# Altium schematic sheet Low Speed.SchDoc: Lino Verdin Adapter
size A3; Organization: Toradex AG; Address1: Ebenaustrasse 10; Address2: Horw; Address3: 6048; Address4: Switzerland; DocumentNumber: 4; Revision: V1.1; SheetNumber: 4; SheetTotal: 8; PageSetup: Record=PageOptions¦CenterHorizontal=True¦CenterVertical=True¦PrintScale=0.73¦XCorrection=1.00¦YCorrection=1.00¦PrintKind=0¦BorderSize=5000000¦LeftOffset=0¦BottomOffset=0¦Orientation=2¦PaperLength=1000¦PaperWidth=1000¦Scale=100¦PaperSource=7¦PrintQuality=-4¦MediaType=1¦DitherType=10¦PaperKind=A4¦PrintScaleMode=1
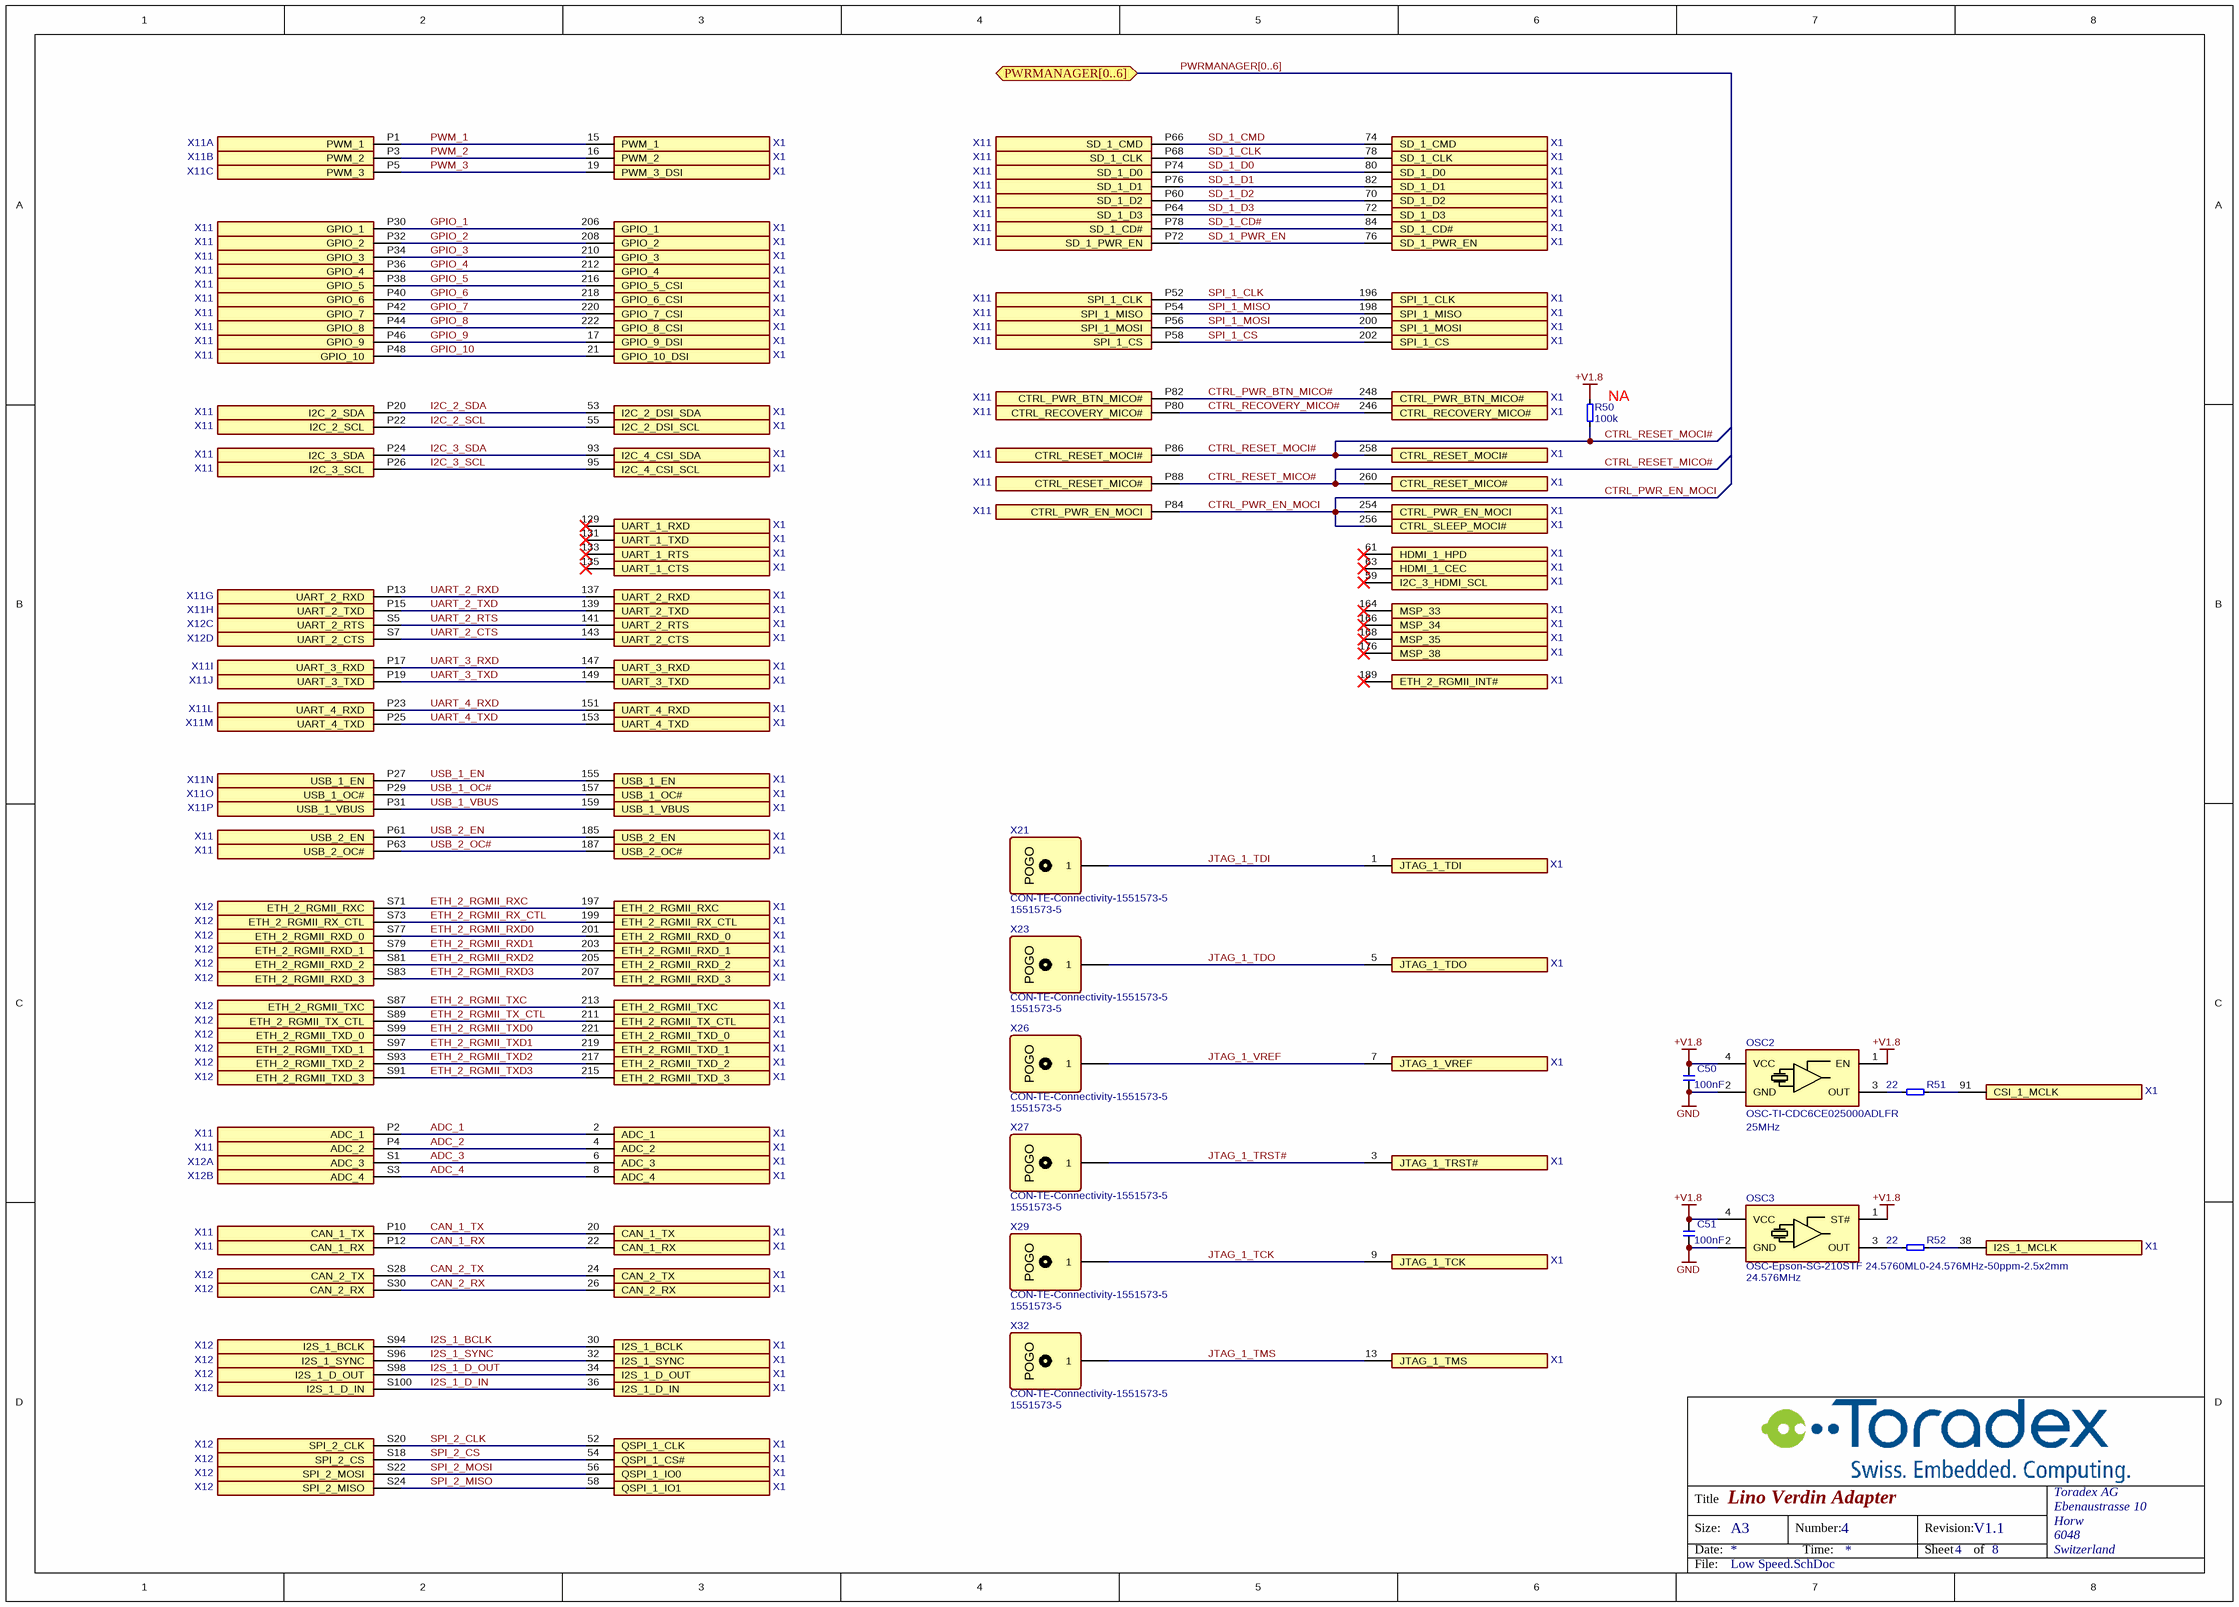
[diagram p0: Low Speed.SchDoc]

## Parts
C50  value 100nF  [CAPC60X30X33L15L]  (hidden comment: C-X5R-100n-6.3V-10%-0201)
C51  value 100nF  [CAPC60X30X33L15L]  (hidden comment: C-X5R-100n-6.3V-10%-0201)
OSC2  OSC-TI-CDC6CE025000ADLFR  Frequency: 25MHz  [OSC-SMD-2.5mmx2.0mm - SOM]
OSC3  OSC-Epson-SG-210STF 24.5760ML0-24.576MHz-50ppm-2.5x2mm  value 24.576MHz  [T_Abracon_ASDMB-24.000MHZ-LC-T]
R50  value 100k  [RESC60X30X33L15L]  (hidden comment: R-100K-50mW-1%-0201)
R51  value 22  [RESC60X30X33L15L]  (hidden comment: R-22R-50mW-5%-0201)
R52  value 22  [RESC60X30X33L15L]  (hidden comment: R-22R-50mW-5%-0201)
X1  CON-SODIMM-DDR4-TEST  [SODIMM_DDR4_no_Module]  (value not drawn)  (parts A,B,E,T,U,V,W,X,27,28,29,30,32,33,34,35,36,52,54,55,56,70,71,72,88,89,90,91,92,93,94,95,97,98,99,100,101,102,103,115,116,117,121,122,123,124,125,126,128,129,130,131,132,152,153,154,155,158,160,161,162,163,165,166,167,168,169,176,177,178,179,184,185,186,187,188,189,190,191,230,231,232,235,245,246,247,248,250,251,252,253,255,256,257,258,260 of 260)  (no BOM)
X11  CON-LINO-P-CARRIER  [HIROSE_DF40C_100DS_LINO_CARRIER_PRIMARY]  (value not drawn)  (parts A,B,C,G,H,I,J,L,M,N,O,P,31,32,51,52,55,56,60,61,62,63,65,66,67,68,69,70,71,72,73,74,76,77,78,79,80,82,83,84,86,87,88,89,90,91,92,93,94 of 100)
X12  CON-LINO-S-CARRIER  [HIROSE_DF40C_100DS_LINO_CARRIER_SECONDARY]  (value not drawn)  (parts A,B,C,D,36,37,39,40,41,42,44,45,46,47,49,50,59,60,61,62,64,65,97,98,99,100 of 100)
X21  CON-TE-Connectivity-1551573-5  Manufacturer Part No.: 1551573-5  [TE-1551573-5]
X23  CON-TE-Connectivity-1551573-5  Manufacturer Part No.: 1551573-5  [TE-1551573-5]
X26  CON-TE-Connectivity-1551573-5  Manufacturer Part No.: 1551573-5  [TE-1551573-5]
X27  CON-TE-Connectivity-1551573-5  Manufacturer Part No.: 1551573-5  [TE-1551573-5]
X29  CON-TE-Connectivity-1551573-5  Manufacturer Part No.: 1551573-5  [TE-1551573-5]
X32  CON-TE-Connectivity-1551573-5  Manufacturer Part No.: 1551573-5  [TE-1551573-5]

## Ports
PWRMANAGER[0..6] (bidir)

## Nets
+V1.8: C50.2 C51.2 OSC2.1(EN) OSC2.4(VCC) OSC3.1(ST#) OSC3.4(VCC) R50.2
GND: C50.1 C51.1 OSC2.2(GND) OSC3.2(GND)
ADC_1: X1.2(ADC_1) X11.P2(ADC_1)
ADC_2: X1.4(ADC_2) X11.P4(ADC_2)
ADC_3: X1.6(ADC_3) X12.S1(ADC_3)
ADC_4: X1.8(ADC_4) X12.S3(ADC_4)
CAN_1_RX: X1.22(CAN_1_RX) X11.P12(CAN_1_RX)
CAN_1_TX: X1.20(CAN_1_TX) X11.P10(CAN_1_TX)
CAN_2_RX: X1.26(CAN_2_RX) X12.S30(CAN_2_RX)
CAN_2_TX: X1.24(CAN_2_TX) X12.S28(CAN_2_TX)
CTRL_PWR_BTN_MICO#: X1.248(CTRL_PWR_BTN_MICO#) X11.P82(CTRL_PWR_BTN_MICO#)
CTRL_PWR_EN_MOCI: X1.254(CTRL_PWR_EN_MOCI) X1.256(CTRL_SLEEP_MOCI#) X11.P84(CTRL_PWR_EN_MOCI)
CTRL_RECOVERY_MICO#: X1.246(CTRL_RECOVERY_MICO#) X11.P80(CTRL_RECOVERY_MICO#)
CTRL_RESET_MICO#: X1.260(CTRL_RESET_MICO#) X11.P88(CTRL_RESET_MICO#)
CTRL_RESET_MOCI#: R50.1 X1.258(CTRL_RESET_MOCI#) X11.P86(CTRL_RESET_MOCI#)
ETH_2_RGMII_RX_CTL: X1.199(ETH_2_RGMII_RX_CTL) X12.S73(ETH_2_RGMII_RX_CTL)
ETH_2_RGMII_RXC: X1.197(ETH_2_RGMII_RXC) X12.S71(ETH_2_RGMII_RXC)
ETH_2_RGMII_RXD0: X1.201(ETH_2_RGMII_RXD_0) X12.S77(ETH_2_RGMII_RXD_0)
ETH_2_RGMII_RXD1: X1.203(ETH_2_RGMII_RXD_1) X12.S79(ETH_2_RGMII_RXD_1)
ETH_2_RGMII_RXD2: X1.205(ETH_2_RGMII_RXD_2) X12.S81(ETH_2_RGMII_RXD_2)
ETH_2_RGMII_RXD3: X1.207(ETH_2_RGMII_RXD_3) X12.S83(ETH_2_RGMII_RXD_3)
ETH_2_RGMII_TX_CTL: X1.211(ETH_2_RGMII_TX_CTL) X12.S89(ETH_2_RGMII_TX_CTL)
ETH_2_RGMII_TXC: X1.213(ETH_2_RGMII_TXC) X12.S87(ETH_2_RGMII_TXC)
ETH_2_RGMII_TXD0: X1.221(ETH_2_RGMII_TXD_0) X12.S99(ETH_2_RGMII_TXD_0)
ETH_2_RGMII_TXD1: X1.219(ETH_2_RGMII_TXD_1) X12.S97(ETH_2_RGMII_TXD_1)
ETH_2_RGMII_TXD2: X1.217(ETH_2_RGMII_TXD_2) X12.S93(ETH_2_RGMII_TXD_2)
ETH_2_RGMII_TXD3: X1.215(ETH_2_RGMII_TXD_3) X12.S91(ETH_2_RGMII_TXD_3)
GPIO_1: X1.206(GPIO_1) X11.P30(GPIO_1)
GPIO_2: X1.208(GPIO_2) X11.P32(GPIO_2)
GPIO_3: X1.210(GPIO_3) X11.P34(GPIO_3)
GPIO_4: X1.212(GPIO_4) X11.P36(GPIO_4)
GPIO_5: X1.216(GPIO_5_CSI) X11.P38(GPIO_5)
GPIO_6: X1.218(GPIO_6_CSI) X11.P40(GPIO_6)
GPIO_7: X1.220(GPIO_7_CSI) X11.P42(GPIO_7)
GPIO_8: X1.222(GPIO_8_CSI) X11.P44(GPIO_8)
GPIO_9: X1.17(GPIO_9_DSI) X11.P46(GPIO_9)
GPIO_10: X1.21(GPIO_10_DSI) X11.P48(GPIO_10)
I2C_2_SCL: X1.55(I2C_2_DSI_SCL) X11.P22(I2C_2_SCL)
I2C_2_SDA: X1.53(I2C_2_DSI_SDA) X11.P20(I2C_2_SDA)
I2C_3_SCL: X1.95(I2C_4_CSI_SCL) X11.P26(I2C_3_SCL)
I2C_3_SDA: X1.93(I2C_4_CSI_SDA) X11.P24(I2C_3_SDA)
I2S_1_BCLK: X1.30(I2S_1_BCLK) X12.S94(I2S_1_BCLK)
I2S_1_D_IN: X1.36(I2S_1_D_IN) X12.S100(I2S_1_D_IN)
I2S_1_D_OUT: X1.34(I2S_1_D_OUT) X12.S98(I2S_1_D_OUT)
I2S_1_SYNC: X1.32(I2S_1_SYNC) X12.S96(I2S_1_SYNC)
JTAG_1_TCK: X1.9(JTAG_1_TCK) X29.1
JTAG_1_TDI: X1.1(JTAG_1_TDI) X21.1
JTAG_1_TDO: X1.5(JTAG_1_TDO) X23.1
JTAG_1_TMS: X1.13(JTAG_1_TMS) X32.1
JTAG_1_TRST#: X1.3(JTAG_1_TRST#) X27.1
JTAG_1_VREF: X1.7(JTAG_1_VREF) X26.1
PWM_1: X1.15(PWM_1) X11.P1(PWM_1)
PWM_2: X1.16(PWM_2) X11.P3(PWM_2)
PWM_3: X1.19(PWM_3_DSI) X11.P5(PWM_3)
SD_1_CD#: X1.84(SD_1_CD#) X11.P78(SD_1_CD#)
SD_1_CLK: X1.78(SD_1_CLK) X11.P68(SD_1_CLK)
SD_1_CMD: X1.74(SD_1_CMD) X11.P66(SD_1_CMD)
SD_1_D0: X1.80(SD_1_D0) X11.P74(SD_1_D0)
SD_1_D1: X1.82(SD_1_D1) X11.P76(SD_1_D1)
SD_1_D2: X1.70(SD_1_D2) X11.P60(SD_1_D2)
SD_1_D3: X1.72(SD_1_D3) X11.P64(SD_1_D3)
SD_1_PWR_EN: X1.76(SD_1_PWR_EN) X11.P72(SD_1_PWR_EN)
SPI_1_CLK: X1.196(SPI_1_CLK) X11.P52(SPI_1_CLK)
SPI_1_CS: X1.202(SPI_1_CS) X11.P58(SPI_1_CS)
SPI_1_MISO: X1.198(SPI_1_MISO) X11.P54(SPI_1_MISO)
SPI_1_MOSI: X1.200(SPI_1_MOSI) X11.P56(SPI_1_MOSI)
SPI_2_CLK: X1.52(QSPI_1_CLK) X12.S20(SPI_2_CLK)
SPI_2_CS: X1.54(QSPI_1_CS#) X12.S18(SPI_2_CS)
SPI_2_MISO: X1.58(QSPI_1_IO1) X12.S24(SPI_2_MISO)
SPI_2_MOSI: X1.56(QSPI_1_IO0) X12.S22(SPI_2_MOSI)
UART_2_CTS: X1.143(UART_2_CTS) X12.S7(UART_2_CTS)
UART_2_RTS: X1.141(UART_2_RTS) X12.S5(UART_2_RTS)
UART_2_RXD: X1.137(UART_2_RXD) X11.P13(UART_2_RXD)
UART_2_TXD: X1.139(UART_2_TXD) X11.P15(UART_2_TXD)
UART_3_RXD: X1.147(UART_3_RXD) X11.P17(UART_3_RXD)
UART_3_TXD: X1.149(UART_3_TXD) X11.P19(UART_3_TXD)
UART_4_RXD: X1.151(UART_4_RXD) X11.P23(UART_4_RXD)
UART_4_TXD: X1.153(UART_4_TXD) X11.P25(UART_4_TXD)
USB_1_EN: X1.155(USB_1_EN) X11.P27(USB_1_EN)
USB_1_OC#: X1.157(USB_1_OC#) X11.P29(USB_1_OC#)
USB_1_VBUS: X1.159(USB_1_VBUS) X11.P31(USB_1_VBUS)
USB_2_EN: X1.185(USB_2_EN) X11.P61(USB_2_EN)
USB_2_OC#: X1.187(USB_2_OC#) X11.P63(USB_2_OC#)
NetOSC2_3: OSC2.3(OUT) R51.1
NetOSC3_3: OSC3.3(OUT) R52.1
NetR51_2: R51.2 X1.91(CSI_1_MCLK)
NetR52_2: R52.2 X1.38(I2S_1_MCLK)

Not connected (* = marked no-connect by the designer): X1 59(I2C_3_HDMI_SCL)* 61(HDMI_1_HPD)* 63(HDMI_1_CEC)* 129(UART_1_RXD)* 131(UART_1_TXD)* 133(UART_1_RTS)* 135(UART_1_CTS)* 164(MSP_33)* 166(MSP_34)* 168(MSP_35)* 176(MSP_38)* 189(ETH_2_RGMII_INT#)*

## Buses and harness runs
bus PWRMANAGER[0..6] = port PWRMANAGER[0..6]

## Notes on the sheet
- (near R50) NA

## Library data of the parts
C50 C51 = CMP-00475-11: Capacitor Ceramic X5R 100nF 6.3V 20% 0201; Manufacturer Name: Generic; Tolerance: 10%
OSC2 = CMP-00761-5: 25MHz Low Power LVCMOS output BAW Oscillator; Manufacturer Name: Texas Instruments
OSC3 = CMP-00985-1: 24.576MHz Oscillator, 2.5x2.0mm, 50ppm, 1.8V-3.3V, -40C to +85C; Manufacturer Name: Epson; Frequency Stability: 50
R50 = CMP-00436-14: Resistor 100K ohm 50mW 1% 0201; Manufacturer Name: Generic
R51 R52 = CMP-00430-14: Resistor 22 ohm 50mW 5% 0201; Manufacturer Name: Generic
X1 = CMP-00731-8: DDR4 SODIMM Card Edge, 260 pins, 0.5mm Pitch; Manufacturer Name: Generic; Manufacturer Part No.: No Physical Component; Gender: Male
X11 = CMP-00961-5: LINO Primary Connector Carrier; Manufacturer Name: Amphenol; Manufacturer Part No.: 10164227-1001A1RLF; Rows: 2
X12 = CMP-00962-5: LINO Secondary Connector; Manufacturer Part No.: 10164227-1001A1RLF; Manufacturer Name: Amphenol; Rows: 2
X21 X23 X26 X27 X29 X32 = CMP-00967-1: Single C-Clip Spring Contact, 1.9 mm High, 1.3mm Low, 2.15 mm Uncompressed Height, 3.26 mm Length; Gender: Male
